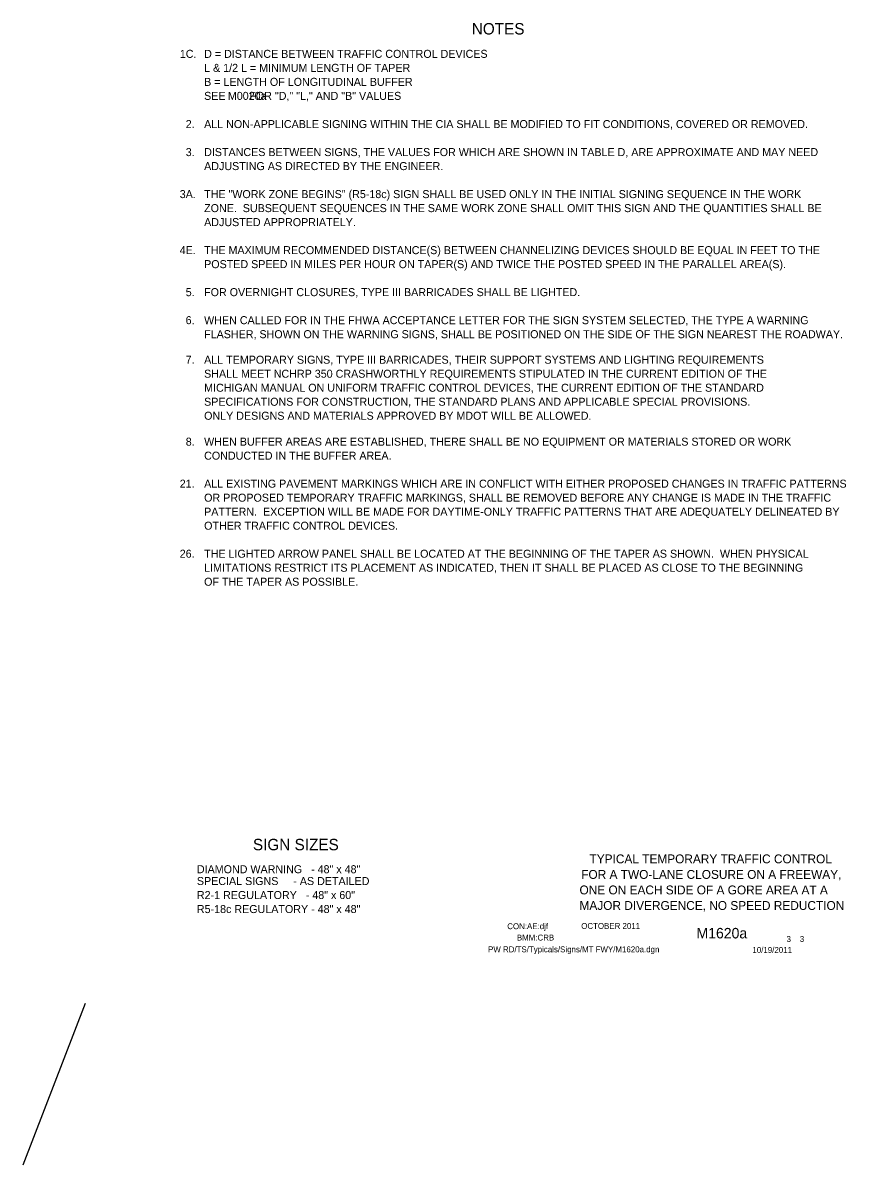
# Model space of a CAD drawing. Extents: x 16604 to 19504, y 6997 to 8305.
# Drawn here: x 18641 to 19504, y 6997 to 8195 of the extents above; entities that cross this region are included whole.
import ezdxf

# ---------------------------------------------------------------- set-up
doc = ezdxf.new("R2010")
doc.units = 0
for name, color, linetype in [('BORDER', 7, 'Continuous'), ('BORDER_SIGNAL_WO', 7, 'Continuous'), ('TYPICAL_TEXT_DIMEN_PR', 7, 'Continuous')]:
    doc.layers.add(name, color=color, linetype=linetype)

msp = doc.modelspace()

# ---------------------------------------------------------------- linework, layer by layer
at = {"layer": 'BORDER'}
msp.add_line((18952.7, 7339.4), (18952.7, 7339.4), dxfattribs=at)
at = {"layer": 'TYPICAL_TEXT_DIMEN_PR'}
msp.add_line((18705.8, 7166.2), (18640.5, 6996.6), dxfattribs=at)

# ---------------------------------------------------------------- texts
at = {"layer": 'BORDER'}
for s, p in [('TYPICAL TEMPORARY TRAFFIC CONTROL', (19235, 7313.4)), ('FOR A TWO-LANE CLOSURE ON A FREEWAY,', (19226.3, 7297.1)), ('ONE ON EACH SIDE OF A GORE AREA AT A', (19224.5, 7280.8)), ('MAJOR DIVERGENCE, NO SPEED REDUCTION', (19224.5, 7264.5))]:
    msp.add_text(s, height=9.3, dxfattribs=at).set_placement(p)
at = {"layer": 'BORDER_SIGNAL_WO'}
for s, height, p in [('CON:AE:djf  ', 6.2, (19148.7, 7244.3)), ('    OCTOBER 2011    ', 6.2, (19217.1, 7244.6)), ('    M1620a   ', 11, (19330.9, 7234.6)), ('BMM:CRB   ', 6.2, (19158.8, 7232.4)), (' 3    3 ', 6.2, (19439.4, 7230.9)), ('PW RD/TS/Typicals/Signs/MT FWY/M1620a.dgn      ', 6.2, (19128.6, 7220)), ('10/19/2011    ', 6.2, (19405.9, 7219.4))]:
    msp.add_text(s, height=height, dxfattribs=at).set_placement(p)
at = {"layer": 'TYPICAL_TEXT_DIMEN_PR'}
for s, height, p in [('NOTES', 12, (19111.5, 8183.2)), ('1C.', 8.4, (18805.2, 8158.7)), ('D = DISTANCE BETWEEN TRAFFIC CONTROL DEVICES', 8.4, (18830.7, 8158.7)), ('L & 1/2 L = MINIMUM LENGTH OF TAPER', 8.4, (18830.7, 8144)), ('B = LENGTH OF LONGITUDINAL BUFFER', 8.4, (18830.7, 8129.3)), ('SEE        FOR "D," "L," AND "B" VALUES', 8.4, (18830.7, 8114.6)), ('M0020a', 8.4, (18855.6, 8114.6)), ('2.', 8.4, (18811.4, 8085)), ('ALL NON-APPLICABLE SIGNING WITHIN THE CIA SHALL BE MODIFIED TO FIT CONDITIONS, COVERED OR REMOVED.', 8.4, (18830.7, 8085)), ('3.', 8.4, (18811.4, 8055.6)), ('DISTANCES BETWEEN SIGNS, THE VALUES FOR WHICH ARE SHOWN IN TABLE D, ARE APPROXIMATE AND MAY NEED', 8.4, (18830.7, 8055.6)), ('ADJUSTING AS DIRECTED BY THE ENGINEER.', 8.4, (18830.7, 8040.9)), ('3A.', 8.4, (18805.1, 8011.5)), ('THE "WORK ZONE BEGINS" (R5-18c) SIGN SHALL BE USED ONLY IN THE INITIAL SIGNING SEQUENCE IN THE WORK', 8.4, (18830.7, 8011.5)), ('ZONE.  SUBSEQUENT SEQUENCES IN THE SAME WORK ZONE SHALL OMIT THIS SIGN AND THE QUANTITIES SHALL BE', 8.4, (18830.7, 7996.8)), ('ADJUSTED APPROPRIATELY.', 8.4, (18830.7, 7982.1)), ('4E.', 8.4, (18805.1, 7952.7)), ('THE MAXIMUM RECOMMENDED DISTANCE(S) BETWEEN CHANNELIZING DEVICES SHOULD BE EQUAL IN FEET TO THE', 8.4, (18830.7, 7952.7)), ('POSTED SPEED IN MILES PER HOUR ON TAPER(S) AND TWICE THE POSTED SPEED IN THE PARALLEL AREA(S).', 8.4, (18830.7, 7938)), ('5.', 8.4, (18811.4, 7908.6)), ('FOR OVERNIGHT CLOSURES, TYPE III BARRICADES SHALL BE LIGHTED. ', 8.4, (18830.7, 7908.6)), ('6.', 8.4, (18811.3, 7879.2)), ('WHEN CALLED FOR IN THE FHWA ACCEPTANCE LETTER FOR THE SIGN SYSTEM SELECTED, THE TYPE A WARNING ', 8.4, (18830.7, 7879.2)), ('FLASHER, SHOWN ON THE WARNING SIGNS, SHALL BE POSITIONED ON THE SIDE OF THE SIGN NEAREST THE ROADWAY.', 8.4, (18830.7, 7864.5)), ('7.', 8.4, (18811.3, 7837.7)), ('ALL TEMPORARY SIGNS, TYPE III BARRICADES, THEIR SUPPORT SYSTEMS AND LIGHTING REQUIREMENTS', 8.4, (18830.7, 7837.7)), ('SHALL MEET NCHRP 350 CRASHWORTHLY REQUIREMENTS STIPULATED IN THE CURRENT EDITION OF THE', 8.4, (18830.7, 7823)), ('MICHIGAN MANUAL ON UNIFORM TRAFFIC CONTROL DEVICES, THE CURRENT EDITION OF THE STANDARD', 8.4, (18830.7, 7808.3)), ('SPECIFICATIONS FOR CONSTRUCTION, THE STANDARD PLANS AND APPLICABLE SPECIAL PROVISIONS.', 8.4, (18830.7, 7793.6)), ('ONLY DESIGNS AND MATERIALS APPROVED BY MDOT WILL BE ALLOWED.', 8.4, (18830.7, 7778.9)), ('8.', 8.4, (18811.4, 7751.7)), ('WHEN BUFFER AREAS ARE ESTABLISHED, THERE SHALL BE NO EQUIPMENT OR MATERIALS STORED OR WORK     ', 8.4, (18830.7, 7751.7)), ('CONDUCTED IN THE BUFFER AREA.', 8.4, (18830.7, 7737)), ('21.', 8.4, (18805.1, 7707.6)), ('ALL EXISTING PAVEMENT MARKINGS WHICH ARE IN CONFLICT WITH EITHER PROPOSED CHANGES IN TRAFFIC PATTERNS', 8.4, (18830.7, 7707.6)), ('OR PROPOSED TEMPORARY TRAFFIC MARKINGS, SHALL BE REMOVED BEFORE ANY CHANGE IS MADE IN THE TRAFFIC', 8.4, (18830.7, 7692.9)), ('PATTERN.  EXCEPTION WILL BE MADE FOR DAYTIME-ONLY TRAFFIC PATTERNS THAT ARE ADEQUATELY DELINEATED BY', 8.4, (18830.7, 7678.2)), ('OTHER TRAFFIC CONTROL DEVICES.', 8.4, (18830.7, 7663.5)), ('26.', 8.4, (18805.1, 7634.1)), ('THE LIGHTED ARROW PANEL SHALL BE LOCATED AT THE BEGINNING OF THE TAPER AS SHOWN.  WHEN PHYSICAL', 8.4, (18830.7, 7634.1)), ('LIMITATIONS RESTRICT ITS PLACEMENT AS INDICATED, THEN IT SHALL BE PLACED AS CLOSE TO THE BEGINNING', 8.4, (18830.7, 7619.4)), ('OF THE TAPER AS POSSIBLE.', 8.4, (18830.7, 7604.7)), ('SIGN SIZES', 12, (18881.9, 7327.1)), ('DIAMOND WARNING   - 48" x 48"', 8.4, (18823.1, 7303)), ('SPECIAL SIGNS     - AS DETAILED', 8.4, (18823.1, 7290.6)), ('R2-1 REGULATORY   - 48" x 60"', 8.4, (18823.1, 7275.9)), ('R5-18c REGULATORY - 48" x 48"', 8.4, (18823.1, 7261.2))]:
    msp.add_text(s, height=height, dxfattribs=at).set_placement(p)

doc.saveas('drawing.dxf')
